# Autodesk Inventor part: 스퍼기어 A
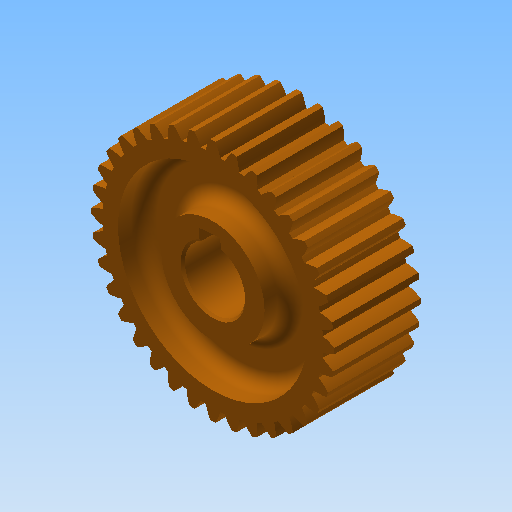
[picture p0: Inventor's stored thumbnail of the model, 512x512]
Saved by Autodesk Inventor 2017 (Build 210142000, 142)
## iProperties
Created: 2020-04
Part Number: 스퍼기어 A
Material: Steel
Document SubType Name: Modeling
Designer: mduedu
Categories: <?xml version="1.0" encoding="UTF-16"?> <MemberInstance><Categories><FamilyTemplate><FamilyTemplateParameter ValueType="xs:double" Id="1" ObjectReferenceKey="da
Density: 7.85 g/cm^3
Mass: 238.004 g
Surface Area: 130.635 cm^2
Volume: 30.319 cm^3
Appearance: 주황색
CustomPartVersion: 1
Author: mduedu
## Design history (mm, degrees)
sketch "Sketch1"
  geometry: C1 r 28.2 at (0, 0)
  constraints: 1 centre point
  dimensions: "d0" = 56.4 diameter of C1 (= da_da)
extrude "Extrusion1" new body sketch "Sketch1" distance "d1" = 20 (= da_b); taper "d2" = 0 deg
workplane "Work Plane2"
sketch "Sketch2"
  geometry: C1 r 28.2 at (0, 0) reference; C2 r 27 at (0, 0)
  constraints: 1 centre point, 1 coincident
  dimensions: "d3" = 54 diameter of C2 (= da_dw)
feature "피치 지름" sketch "Sketch2" dims "d4" = 10, "d5" = 0
workplane "Work Plane8"
workplane "Work Plane9"
feature "스퍼 기어" dims "da_b" = 20, "da_d" = 54, "da_aw" = 45, "da_da" = 56.4, "da_df" = 51.129, "da_dw" = 54, angle "da_beta" = 0 deg, "da_lefttooth" = 0, "da_righttooth" = 0
node "작업 평면11"
sketch "스케치3"
  geometry: C1 r 12 at (0, 0); C2 r 22 at (0, 0); 1 further point
  constraints: 2 centre point, 2 coincident
  dimensions: "d49" = 24 diameter of C1; "d50" = 44 diameter of C2
extrude "돌출2" cut sketch "스케치3" distance "d51" = 6; taper "d52" = 0 deg
fillet "모깎기1" dims "d53" = 3
sketch "스케치4" dims "d17" = 0
  geometry: L1 (-3.06, 6.296)-(1.921, 6.731); L2 (1.921, 6.731)-(1.68, 9.483); L3 (1.68, 9.483)-(-3.301, 9.047); L4 (-3.301, 9.047)-(-3.06, 6.296); L5 (-3.728, 42.608)-(3.728, -42.608) reference; A1 r 7 centre (0, 0) between (-3.06, 6.296) and (1.921, 6.731); 1 further point
  constraints: 8 end point, 4 perpendicular, 2 point on circle, 1 centre point, 1 coincident
  dimensions: "d54" = 14 diameter of A1; "d63" = 16.3 dimension on A1 L3; "d64" = 5 distance of L2.end L3.end
extrude "돌출3" cut sketch "스케치4" stored distance "d58" = 6; taper "d59" = 0 deg
chamfer "모따기1" distance "d60" = 0.5; stored, may be unused: second distance "d61" = 2, angle "d62" = 45 deg
body "Solid1"
mirror "대칭1"
body "Srf1"
other parameters: "d16" = 45 (= da_aw), "d34" = 5 deg (computed from da_z), "d39" = 0, "d41" = 0, "d43" = 45 (= da_aw), "d46" = 45 (= da_aw), "d47" = 0, "d48" = 0
